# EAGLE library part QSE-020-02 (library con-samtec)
0,80mm HI-SPEED SOCKET QSE Serie Source: http://www.samtec.com/ftppub/cpdf/QSE-XXX-01-X-D-XX-FOOTPRINT.pdf http://www.samtec.com/ftppub/pdf/QSE.PDF
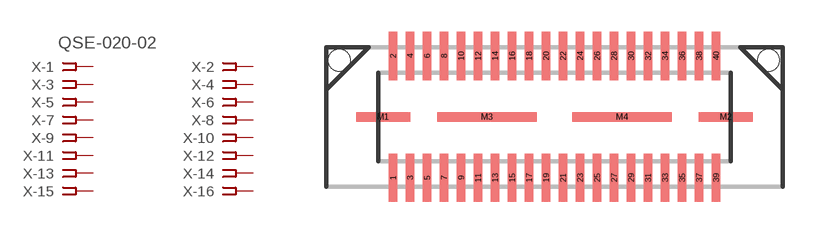
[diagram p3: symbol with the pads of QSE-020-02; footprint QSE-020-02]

Designator prefix X; gates -1=FPINV -2=FPIN -3=FPIN -4=FPIN -5=FPIN -6=FPIN -7=FPIN -8=FPIN -9=FPIN -10=FPIN -11=FPIN -12=FPIN -13=FPIN -14=FPIN -15=FPIN -16=FPIN -17=FPIN -18=FPIN -19=FPIN -20=FPIN -21=FPIN -22=FPIN -23=FPIN -24=FPIN -25=FPIN -26=FPIN -27=FPIN -28=FPIN -29=FPIN -30=FPIN -31=FPIN -32=FPIN -33=FPIN -34=FPIN -35=FPIN -36=FPIN -37=FPIN -38=FPIN -39=FPIN -40=FPIN

## QSE-020-02 (OC_FARNELL: unknown; OC_NEWARK: unknown)  [QSE-020-02]
1  -1:1  pas
2  -2:1  pas
3  -3:1  pas
4  -4:1  pas
5  -5:1  pas
6  -6:1  pas
7  -7:1  pas
8  -8:1  pas
9  -9:1  pas
10  -10:1  pas
11  -11:1  pas
12  -12:1  pas
13  -13:1  pas
14  -14:1  pas
15  -15:1  pas
16  -16:1  pas
17  -17:1  pas
18  -18:1  pas
19  -19:1  pas
20  -20:1  pas
21  -21:1  pas
22  -22:1  pas
23  -23:1  pas
24  -24:1  pas
25  -25:1  pas
26  -26:1  pas
27  -27:1  pas
28  -28:1  pas
29  -29:1  pas
30  -30:1  pas
31  -31:1  pas
32  -32:1  pas
33  -33:1  pas
34  -34:1  pas
35  -35:1  pas
36  -36:1  pas
37  -37:1  pas
38  -38:1  pas
39  -39:1  pas
40  -40:1  pas

## Footprint QSE-020-02 (pad centres in mm)
0,80mm HI-SPEED SOCKET QSE Serie Source: http://www.samtec.com/ftppub/cpdf/QSE-XXX-01-X-D-XX-FOOTPRINT.pdf http://www.samtec.com/ftppub/pdf/QSE.PDF
smd 0.41 x 2.27: 1 -7.595,-2.86; 2 -7.595,2.87; 3 -6.795,-2.86; 4 -6.795,2.87; 5 -5.995,-2.86; 6 -5.995,2.87; 7 -5.195,-2.86; 8 -5.195,2.87; 9 -4.395,-2.86; 10 -4.395,2.87; 11 -3.595,-2.86; 12 -3.595,2.87; 13 -2.795,-2.86; 14 -2.795,2.87; 15 -1.995,-2.86; 16 -1.995,2.87; 17 -1.195,-2.86; 18 -1.195,2.87; 19 -0.395,-2.86; 20 -0.395,2.87; 21 0.405,-2.86; 22 0.405,2.87; 23 1.205,-2.86; 24 1.205,2.87; 25 2.005,-2.86; 26 2.005,2.87; 27 2.805,-2.86; 28 2.805,2.87; 29 3.605,-2.86; 30 3.605,2.87; 31 4.405,-2.86; 32 4.405,2.87; 33 5.205,-2.86; 34 5.205,2.87; 35 6.005,-2.86; 36 6.005,2.87; 37 6.805,-2.86; 38 6.805,2.87; 39 7.605,-2.86; 40 7.605,2.87
smd 2.54 x 0.43: M1 -8.065,0; M2 8.065,0
smd 4.7 x 0.43: M3 -3.175,0; M4 3.175,0
hole 1.02 at -10.13,2.67
hole 1.02 at 10.065,2.67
